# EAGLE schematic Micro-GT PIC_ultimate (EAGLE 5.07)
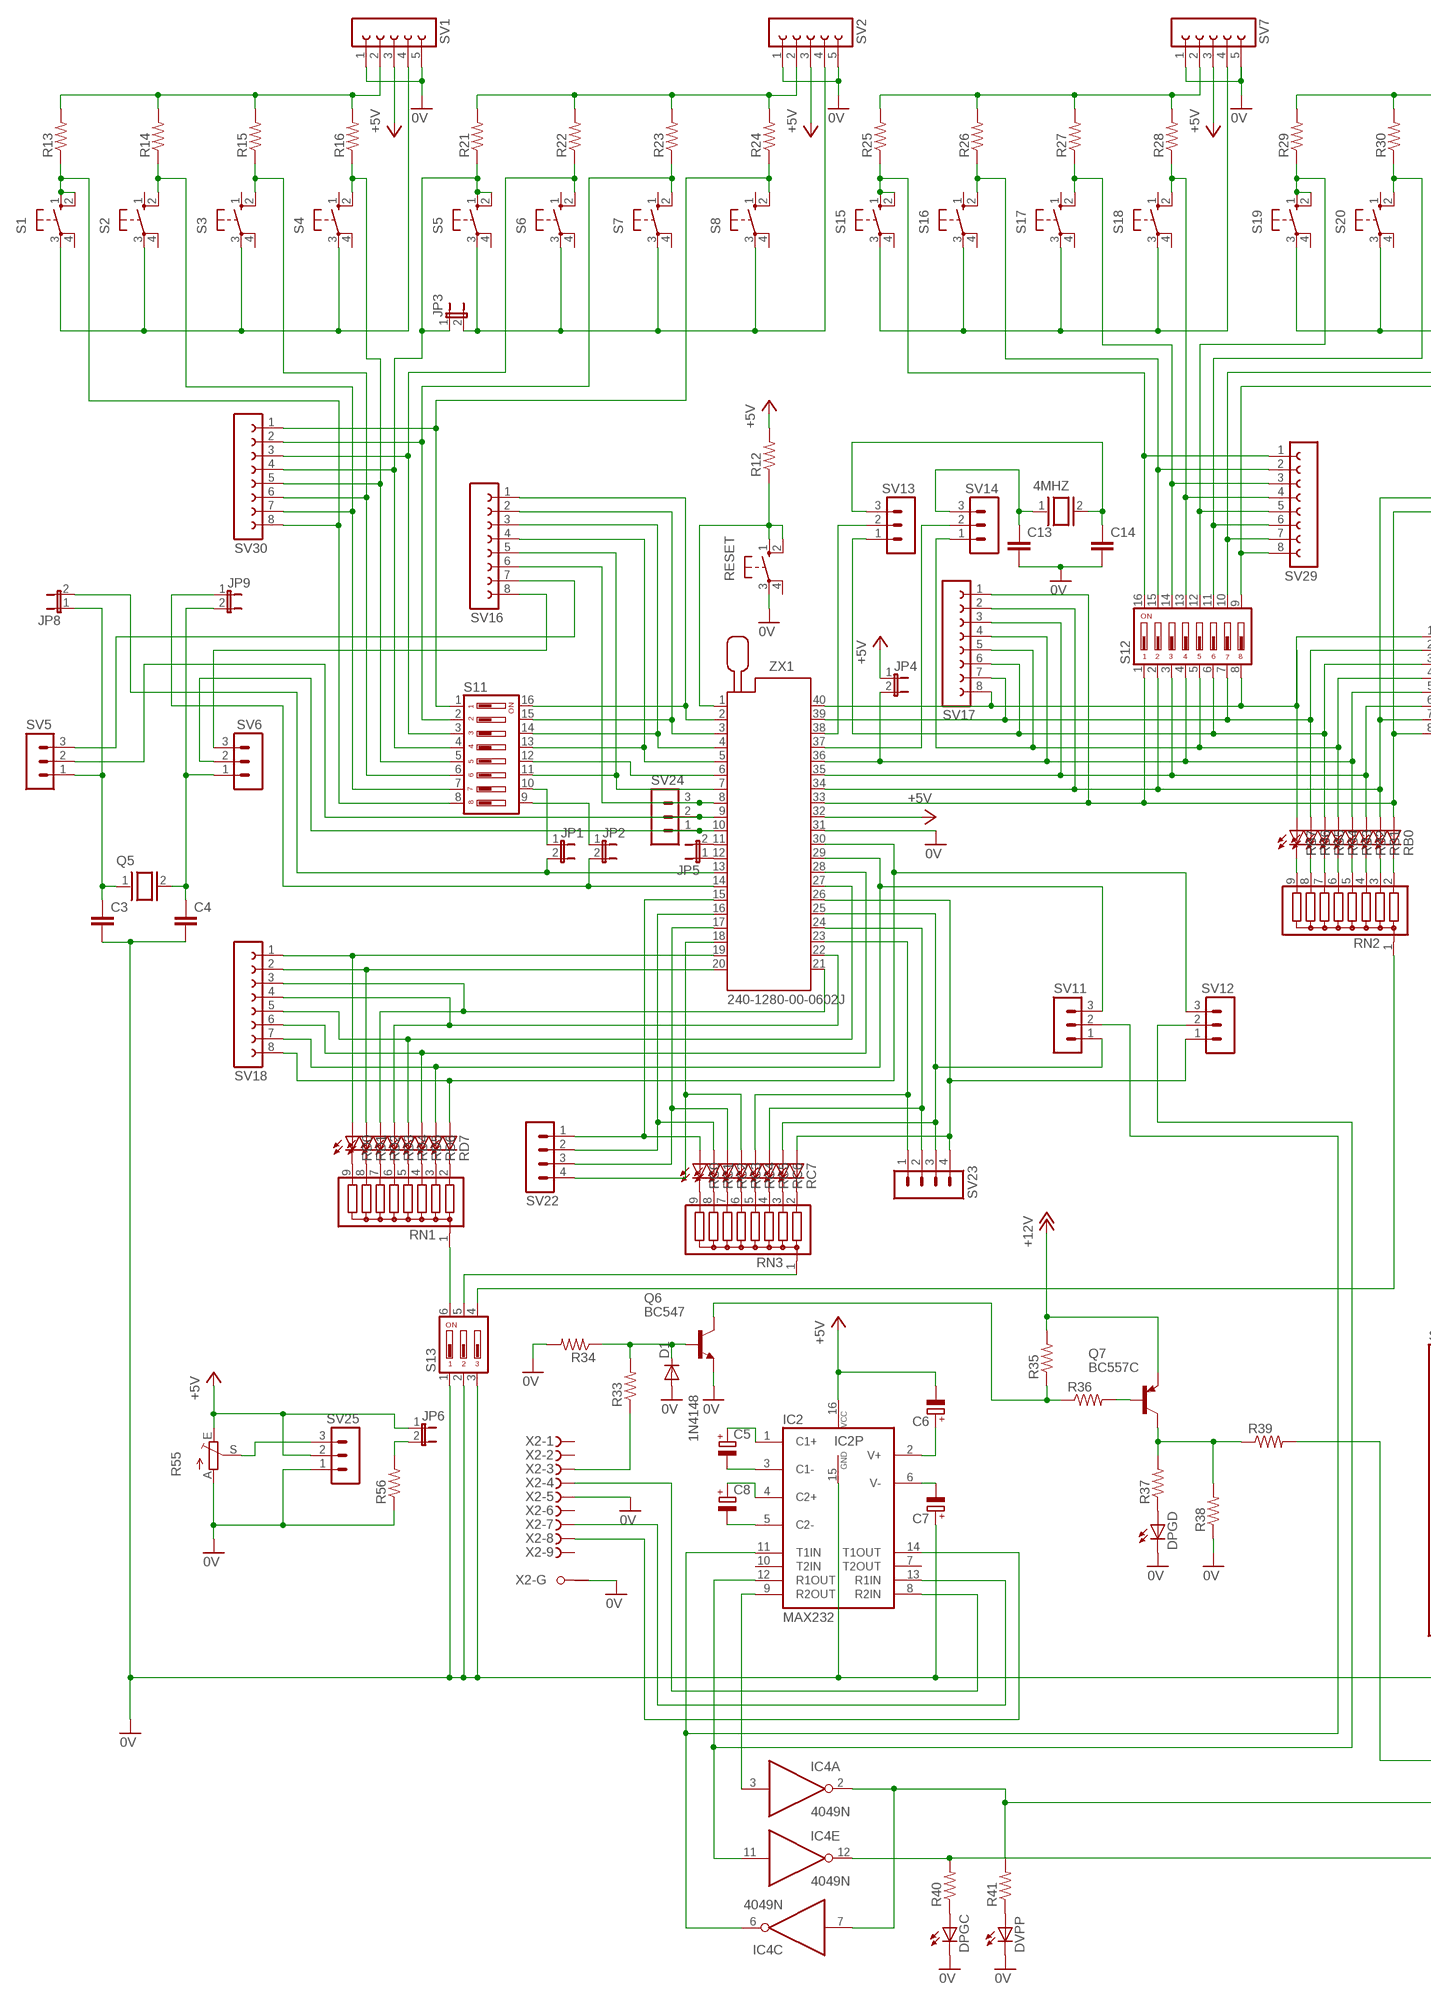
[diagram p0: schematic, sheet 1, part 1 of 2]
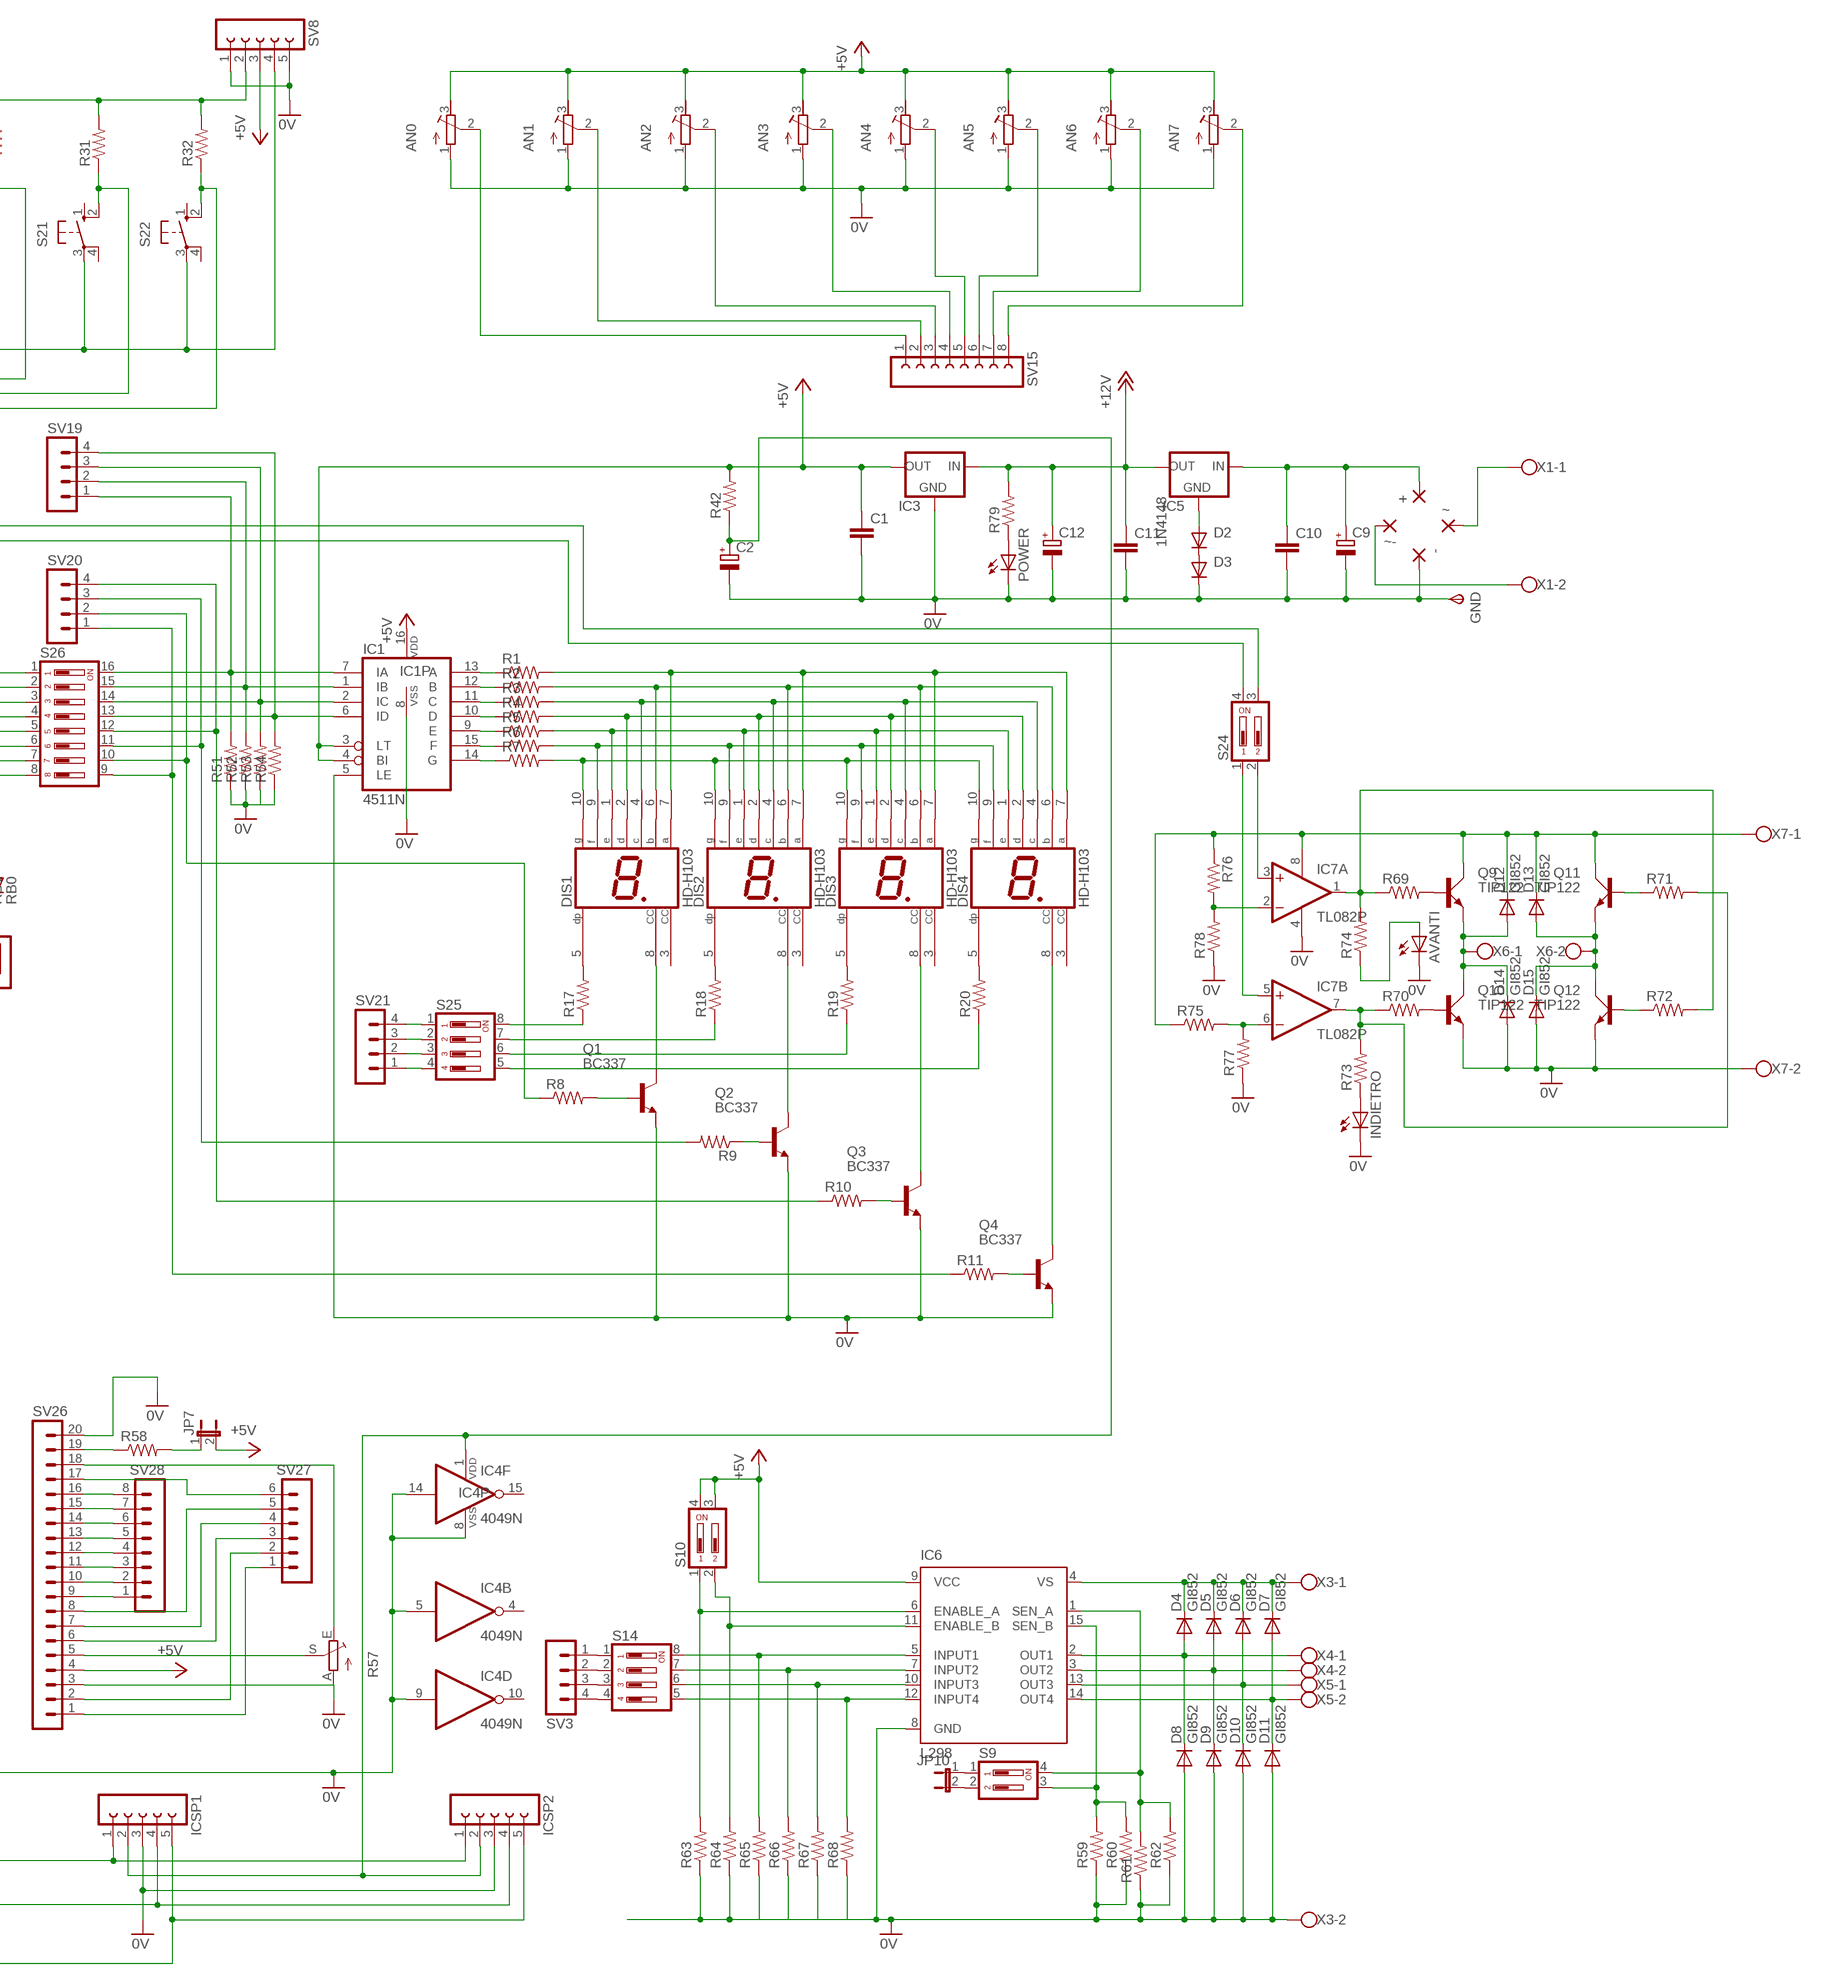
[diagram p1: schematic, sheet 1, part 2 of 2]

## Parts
4MHZ  XTAL/S  [QS]
+  1,6/0,8  [1,6/0,8]
-  1,6/0,8  [1,6/0,8]
AN0  R-TRIMM64W  [RTRIM64W]
AN1  R-TRIMM64W  [RTRIM64W]
AN2  R-TRIMM64W  [RTRIM64W]
AN3  R-TRIMM64W  [RTRIM64W]
AN4  R-TRIMM64W  [RTRIM64W]
AN5  R-TRIMM64W  [RTRIM64W]
AN6  R-TRIMM64W  [RTRIM64W]
AN7  R-TRIMM64W  [RTRIM64W]
AVANTI  LED3MM  [LED3MM]
C1  C-EU050-025X075  [C050-025X075]
C2  CPOL-EUE2.5-5  [E2,5-5]
C3  C2.5/2  [C2.5-2]
C4  C2.5/2  [C2.5-2]
C5  CPOL-EUE2.5-5  [E2,5-5]
C6  CPOL-EUE2.5-5  [E2,5-5]
C7  CPOL-EUE2.5-5  [E2,5-5]
C8  CPOL-EUE2.5-5  [E2,5-5]
C9  CPOL-EUE5-10.5  [E5-10,5]
C10  C-EU050-025X075  [C050-025X075]
C11  C-EU050-025X075  [C050-025X075]
C12  CPOL-EUE2.5-5  [E2,5-5]
C13  C2.5/2  [C2.5-2]
C14  C2.5/2  [C2.5-2]
D1  1N4148  1N4148DO35-7  [DO35-7]
D2  1N4148  1N4148DO35-7  [DO35-7]
D3  1N4148  1N4148DO35-7  [DO35-7]
D4  GI852  1N5400  [DO201-15]
D5  GI852  1N5400  [DO201-15]
D6  GI852  1N5400  [DO201-15]
D7  GI852  1N5400  [DO201-15]
D8  GI852  1N5400  [DO201-15]
D9  GI852  1N5400  [DO201-15]
D10  GI852  1N5400  [DO201-15]
D11  GI852  1N5400  [DO201-15]
D12  GI852  1N5400  [DO201-15]
D13  GI852  1N5400  [DO201-15]
D14  GI852  1N5400  [DO201-15]
D15  GI852  1N5400  [DO201-15]
DIS1  HD-H103  [HDSP-M]
DIS2  HD-H103  [HDSP-M]
DIS3  HD-H103  [HDSP-M]
DIS4  HD-H103  [HDSP-M]
DPGC  LED3MM  [LED3MM]
DPGD  LED3MM  [LED3MM]
DVPP  LED3MM  [LED3MM]
GND  TPSPAD1-13  [P1-13]
IC1  4511N  [DIL16]
IC2  MAX232  [DIL16]
IC3  78XXS  [78XXS]
IC4  4049N  [DIL16]
IC5  78XXS  [78XXS]
IC6  L298  [MULTIWATT-15]
IC7  TL082P  [DIL08]
ICSP1  FE05-1  [FE05-1]
ICSP2  FE05-1  [FE05-1]
INDIETRO  LED3MM  [LED3MM]
JP1  JP1E  [JP1]
JP2  JP1E  [JP1]
JP3  JP1E  [JP1]
JP4  JP1E  [JP1]
JP5  JP1E  [JP1]
JP6  JP1E  [JP1]
JP7  JP1E  [JP1]
JP8  JP1E  [JP1]
JP9  JP1E  [JP1]
JP10  JP1E  [JP1]
POWER  LED3MM  [LED3MM]
Q1  BC337  [TO92]
Q2  BC337  [TO92]
Q3  BC337  [TO92]
Q4  BC337  [TO92]
Q5  XTAL/S  [QS]
Q6  BC547  [TO92]
Q7  BC557C  [TO92-EBC]
Q9  TIP122  TIP41C  [TO220AV]
Q10  TIP122  TIP41C  [TO220AV]
Q11  TIP122  TIP41C  [TO220AV]
Q12  TIP122  TIP41C  [TO220AV]
R1  R-US_0207/10  [0207/10]
R2  R-US_0207/10  [0207/10]
R3  R-US_0207/10  [0207/10]
R4  R-US_0207/10  [0207/10]
R5  R-US_0207/10  [0207/10]
R6  R-US_0207/10  [0207/10]
R7  R-US_0207/10  [0207/10]
R8  R-US_0207/10  [0207/10]
R9  R-US_0207/10  [0207/10]
R10  R-US_0207/10  [0207/10]
R11  R-US_0207/10  [0207/10]
R12  R-US_0207/10  [0207/10]
R13  R-US_0207/10  [0207/10]
R14  R-US_0207/10  [0207/10]
R15  R-US_0207/10  [0207/10]
R16  R-US_0207/10  [0207/10]
R17  R-US_0207/10  [0207/10]
R18  R-US_0207/10  [0207/10]
R19  R-US_0207/10  [0207/10]
R20  R-US_0207/10  [0207/10]
R21  R-US_0207/10  [0207/10]
R22  R-US_0207/10  [0207/10]
R23  R-US_0207/10  [0207/10]
R24  R-US_0207/10  [0207/10]
R25  R-US_0207/10  [0207/10]
R26  R-US_0207/10  [0207/10]
R27  R-US_0207/10  [0207/10]
R28  R-US_0207/10  [0207/10]
R29  R-US_0207/10  [0207/10]
R30  R-US_0207/10  [0207/10]
R31  R-US_0207/10  [0207/10]
R32  R-US_0207/10  [0207/10]
R33  R-US_0207/10  [0207/10]
R34  R-US_0207/10  [0207/10]
R35  R-US_0207/10  [0207/10]
R36  R-US_0207/10  [0207/10]
R37  R-US_0207/10  [0207/10]
R38  R-US_0207/10  [0207/10]
R39  R-US_0207/10  [0207/10]
R40  R-US_0207/10  [0207/10]
R41  R-US_0207/10  [0207/10]
R42  R-US_0207/10  [0207/10]
R51  R-US_0207/10  [0207/10]
R52  R-US_0207/10  [0207/10]
R53  R-US_0207/10  [0207/10]
R54  R-US_0207/10  [0207/10]
R55  TRIM_EU-CA9V  [CA9V]
R56  R-US_0207/10  [0207/10]
R57  TRIM_EU-CA9V  [CA9V]
R58  R-US_0207/10  [0207/10]
R59  R-US_0207/10  [0207/10]
R60  R-US_0207/10  [0207/10]
R61  R-US_0207/10  [0207/10]
R62  R-US_0207/10  [0207/10]
R63  R-US_0207/10  [0207/10]
R64  R-US_0207/10  [0207/10]
R65  R-US_0207/10  [0207/10]
R66  R-US_0207/10  [0207/10]
R67  R-US_0207/10  [0207/10]
R68  R-US_0207/10  [0207/10]
R69  R-US_0207/10  [0207/10]
R70  R-US_0207/10  [0207/10]
R71  R-US_0207/10  [0207/10]
R72  R-US_0207/10  [0207/10]
R73  R-US_0207/10  [0207/10]
R74  R-US_0207/10  [0207/10]
R75  R-US_0207/10  [0207/10]
R76  R-US_0207/10  [0207/10]
R77  R-US_0207/10  [0207/10]
R78  R-US_0207/10  [0207/10]
R79  R-US_0207/10  [0207/10]
RB0  LED3MM  [LED3MM]
RB1  LED3MM  [LED3MM]
RB2  LED3MM  [LED3MM]
RB3  LED3MM  [LED3MM]
RB4  LED3MM  [LED3MM]
RB5  LED3MM  [LED3MM]
RB6  LED3MM  [LED3MM]
RB7  LED3MM  [LED3MM]
RC0  LED3MM  [LED3MM]
RC1  LED3MM  [LED3MM]
RC2  LED3MM  [LED3MM]
RC3  LED3MM  [LED3MM]
RC4  LED3MM  [LED3MM]
RC5  LED3MM  [LED3MM]
RC6  LED3MM  [LED3MM]
RC7  LED3MM  [LED3MM]
RD0  LED3MM  [LED3MM]
RD1  LED3MM  [LED3MM]
RD2  LED3MM  [LED3MM]
RD3  LED3MM  [LED3MM]
RD4  LED3MM  [LED3MM]
RD5  LED3MM  [LED3MM]
RD6  LED3MM  [LED3MM]
RD7  LED3MM  [LED3MM]
RESET  10-XX  [B3F-10XX]
RN1  G08R  [SIL9]
RN2  G08R  [SIL9]
RN3  G08R  [SIL9]
S1  10-XX  [B3F-10XX]
S2  10-XX  [B3F-10XX]
S3  10-XX  [B3F-10XX]
S4  10-XX  [B3F-10XX]
S5  10-XX  [B3F-10XX]
S6  10-XX  [B3F-10XX]
S7  10-XX  [B3F-10XX]
S8  10-XX  [B3F-10XX]
S9  DIP02YL  [DIP02YL]
S10  DIP02YL  [DIP02YL]
S11  DIP08YL  [DIP08YL]
S12  DIP08YL  [DIP08YL]
S13  DIP03YL  [DIP03YL]
S14  DIP04YL  [DIP04YL]
S15  10-XX  [B3F-10XX]
S16  10-XX  [B3F-10XX]
S17  10-XX  [B3F-10XX]
S18  10-XX  [B3F-10XX]
S19  10-XX  [B3F-10XX]
S20  10-XX  [B3F-10XX]
S21  10-XX  [B3F-10XX]
S22  10-XX  [B3F-10XX]
S24  DIP02YL  [DIP02YL]
S25  DIP04YL  [DIP04YL]
S26  DIP08YL  [DIP08YL]
SV1  FE05-1  [FE05-1]
SV2  FE05-1  [FE05-1]
SV3  MA04-1  [MA04-1]
SV5  MA03-1  [MA03-1]
SV6  MA03-1  [MA03-1]
SV7  FE05-1  [FE05-1]
SV8  FE05-1  [FE05-1]
SV11  MA03-1  [MA03-1]
SV12  MA03-1  [MA03-1]
SV13  MA03-1  [MA03-1]
SV14  MA03-1  [MA03-1]
SV15  FE08-1  [FE08]
SV16  FE08-1  [FE08]
SV17  FE08-1  [FE08]
SV18  FE08-1  [FE08]
SV19  MA04-1  [MA04-1]
SV20  MA04-1  [MA04-1]
SV21  MA04-1  [MA04-1]
SV22  MA04-1  [MA04-1]
SV23  MA04-1  [MA04-1]
SV24  MA03-1  [MA03-1]
SV25  MA03-1  [MA03-1]
SV26  MA20-1  [MA20-1]
SV27  MA06-1  [MA06-1]
SV28  MA08-1  [MA08-1]
SV29  FE08-1  [FE08]
SV30  FE08-1  [FE08]
X1  W237-102  [W237-102]
X2  F09HPS  [F09HP]
X3  W237-102  [W237-102]
X4  W237-102  [W237-102]
X5  W237-102  [W237-102]
X6  W237-102  [W237-102]
X7  W237-102  [W237-102]
ZX1  240-1280-00-0602J  [240-1280-00-0602J]
~  1,6/0,8  [1,6/0,8]
~-  1,6/0,8  [1,6/0,8]

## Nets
0V: -.1(P) AN0.1(E) AN1.1(E) AN2.1(E) AN3.1(E) AN4.1(E) AN5.1(E) AN6.1(E) AN7.1(E) AVANTI.K(C) C1.2 C2.- C3.2 C4.2 C7.+ C9.- C10.2 C11.2 C12.- C13.2 C14.2 D1.A D3.C D8.A D9.A D10.A D11.A D14.A D15.A DPGC.K(C) DPGD.K(C) DVPP.K(C) GND.TP(PP) IC1.5(LE) IC1.8(VSS) IC2.15(GND) IC3.GND IC4.5(B:I) IC4.8(P:VSS) IC4.9(D:I) IC4.14(F:I) IC6.8(GND) IC7.4(P:V-) ICSP1.3 ICSP2.3 INDIETRO.K(C) POWER.K(C) Q1.1(E) Q2.1(E) Q3.1(E) Q4.1(E) Q6.1(E) Q10.E Q12.E R34.2 R38.1 R51.1 R52.1 R53.1 R54.1 R55.A R56.1 R57.A R59.1 R60.1 R61.1 R62.1 R63.1 R64.1 R65.1 R66.1 R67.1 R68.1 R77.1 R78.1 RESET.3(P) S13.1 S13.2 S13.3 SV1.1 SV1.5 SV2.1 SV2.5 SV7.1 SV7.5 SV8.1 SV8.5 SV25.1 SV26.3 SV26.20 X2.5(-5:F) X2.G1(-G:G1) X3.2 X7.2 ZX1.31
+5V: AN0.3(A) AN1.3(A) AN2.3(A) AN3.3(A) AN4.3(A) AN5.3(A) AN6.3(A) AN7.3(A) C1.1 C6.- IC1.3(LT) IC1.4(BI) IC1.16(VDD) IC2.16(VCC) IC3.OUT IC6.9(VCC) JP4.1 JP6.1 JP7.2 R12.2 R42.2 R55.E S10.3 S10.4 SV1.3 SV2.3 SV7.3 SV8.3 SV25.2 SV26.4 ZX1.32
+12V: C11.1 C12.+ IC3.IN IC5.OUT Q7.E R35.2 R79.2
N$1: Q2.2(B) R9.1
N$2: Q3.2(B) R10.2
N$3: DIS1.5(DP) R17.2
N$4: POWER.A R79.1
N$5: IC1.13(A) R1.1
N$6: IC1.12(B) R2.1
N$7: IC1.11(C) R3.1
N$8: IC1.10(D) R4.1
N$9: IC1.9(E) R5.1
N$10: IC1.15(F) R6.1
N$11: IC1.14(G) R7.1
N$12: Q1.2(B) R8.2
N$13: DIS2.5(DP) R18.2
N$14: DIS3.5(DP) R19.2
N$15: DIS4.5(DP) R20.2
N$16: DIS1.9(F) DIS2.9(F) DIS3.9(F) DIS4.9(F) R6.2
N$17: DIS1.7(A) DIS2.7(A) DIS3.7(A) DIS4.7(A) R1.2
N$18: DIS1.6(B) DIS2.6(B) DIS3.6(B) DIS4.6(B) R2.2
N$19: DIS1.4(C) DIS2.4(C) DIS3.4(C) DIS4.4(C) R3.2
N$20: DIS1.2(D) DIS2.2(D) DIS3.2(D) DIS4.2(D) R4.2
N$21: DIS1.1(E) DIS2.1(E) DIS3.1(E) DIS4.1(E) R5.2
N$22: DIS1.10(G) DIS2.10(G) DIS3.10(G) DIS4.10(G) R7.2
N$23: IC1.7(IA) R51.2 S26.16 SV19.1
N$24: RN1.1 S13.6
N$25: D2.A IC5.GND
N$26: IC1.1(IB) R52.2 S26.15 SV19.2
N$27: DIS4.8(CC) Q4.3(C)
N$28: S1.3(P) S2.3(P) S3.3(P) S4.3(P) SV1.4
N$29: RN2.1 S13.4
N$30: RC0.K(C) RN3.9
N$31: RC1.K(C) RN3.8
N$32: RC2.K(C) RN3.7
N$33: Q4.2(B) R11.2
N$34: RB7.K(C) RN2.9
N$35: IC2.11(T1IN) IC4.6(C:O) SV11.2
N$36: IC1.2(IC) R53.2 S26.14 SV19.3
N$37: IC1.6(ID) R54.2 S26.13 SV19.4
N$38: R14.1 S2.2(S1) S11.7 SV30.7
N$39: JP1.2 JP8.2 ZX1.13
N$40: R13.1 S1.1(S) S1.2(S1) S11.8 SV30.8
N$41: JP2.2 JP9.1 ZX1.14
N$42: SV5.2 SV24.2 ZX1.9
N$43: R16.1 S4.2(S1) S11.5 SV30.5
N$44: RB6.K(C) RN2.8
N$45: C4.1 JP9.2 Q5.2 SV6.1
N$46: C3.1 JP8.1 Q5.1 SV5.1
N$47: R8.1 S26.10 SV20.2
N$48: RC3.K(C) RN3.6
N$49: RC4.K(C) RN3.5
N$50: R11.1 S26.9 SV20.1
N$51: R17.1 S25.8
N$52: R18.1 S25.7
N$53: DIS1.8(CC) Q1.3(C)
N$54: DIS2.8(CC) Q2.3(C)
N$55: DIS3.8(CC) Q3.3(C)
N$56: RC5.K(C) RN3.4
N$57: R19.1 S25.6
N$58: R20.1 S25.5
N$59: R21.2 R22.2 R23.2 R24.2 SV2.2
N$60: JP3.2 S5.3(P) S6.3(P) S7.3(P) S8.3(P) SV2.4
N$61: JP3.1 R21.1 S5.1(S) S5.2(S1) S11.4 SV30.4
N$62: R22.1 S6.2(S1) S11.3 SV30.3
N$63: R23.1 S7.2(S1) S11.2 SV30.2
N$64: R24.1 S8.2(S1) S11.1 SV30.1
N$65: RD0.K(C) RN1.9
N$66: R13.2 R14.2 R15.2 R16.2 SV1.2
N$67: R15.1 S3.2(S1) S11.6 SV30.6
N$68: SV6.2 SV24.1 ZX1.10
N$69: R25.1 S12.16 S15.1(S) S15.2(S1) SV29.1
N$70: R28.1 S12.13 S18.2(S1) SV29.4
N$71: R29.2 R30.2 R31.2 R32.2 SV8.2
N$72: S19.3(P) S20.3(P) S21.3(P) S22.3(P) SV8.4
N$73: R29.1 S12.12 S19.1(S) S19.2(S1) SV29.5
N$74: R30.1 S12.11 S20.2(S1) SV29.6
N$75: R31.1 S12.10 S21.2(S1) SV29.7
N$76: R32.1 S12.9 S22.2(S1) SV29.8
N$77: R25.2 R26.2 R27.2 R28.2 SV7.2
N$78: R26.1 S12.15 S16.2(S1) SV29.2
N$79: R27.1 S12.14 S17.2(S1) SV29.3
N$80: RD1.K(C) RN1.8
N$81: S11.16 SV16.1 ZX1.2
N$82: S11.15 SV16.2 ZX1.3
N$83: S11.14 SV16.3 ZX1.4
N$84: S11.13 SV16.4 ZX1.5
N$85: S11.12 ZX1.6
N$86: S11.11 SV16.5 ZX1.7
N$87: R12.1 RESET.1(S) RESET.2(S1) ZX1.1
N$88: RD2.K(C) RN1.7
N$89: RD3.K(C) RN1.6
N$90: JP1.1 S11.10
N$91: JP2.1 S11.9
N$92: RD4.K(C) RN1.5
N$93: RD5.K(C) RN1.4
N$94: RD6.K(C) RN1.3
N$95: RD7.K(C) RN1.2
N$96: RD0.A SV18.1 ZX1.19
N$97: S15.3(P) S16.3(P) S17.3(P) S18.3(P) SV7.4
N$98: RD1.A SV18.2 ZX1.20
N$99: RD2.A SV18.3 ZX1.21
N$100: RD3.A SV18.4 ZX1.22
N$101: RD4.A SV18.5 ZX1.27
N$102: RD5.A SV18.6 ZX1.28
N$103: RD6.A SV11.3 SV18.7 ZX1.29
N$104: RD7.A SV12.3 SV18.8 ZX1.30
N$105: RB5.K(C) RN2.7
N$106: RB4.K(C) RN2.6
N$107: RB3.K(C) RN2.5
N$108: RB2.K(C) RN2.4
N$109: RB1.K(C) RN2.3
N$110: RB0.K(C) RN2.2
N$111: RB7.A S12.8 S26.1 SV17.8 ZX1.40
N$112: RB6.A S12.7 S26.2 SV17.7 ZX1.39
N$114: RB4.A S12.5 S26.4 SV14.1 SV17.5
N$115: JP4.2 RB3.A S12.4 S26.5 SV17.4 ZX1.36
N$116: RB2.A S12.3 S26.6 SV17.3 ZX1.35
N$117: RB1.A S12.2 S24.3 S26.7 SV17.2 ZX1.34
N$118: RB0.A S12.1 S24.4 S26.8 SV17.1 ZX1.33
N$119: RC6.K(C) RN3.3
N$120: RC7.K(C) RN3.2
N$121: RC0.A SV22.1 ZX1.15
N$122: RC1.A SV22.2 ZX1.16
N$123: RC2.A SV22.3 ZX1.17
N$124: RC3.A SV22.4 ZX1.18
N$125: RC4.A SV23.1 ZX1.23
N$126: RC5.A SV23.2 ZX1.24
N$127: RC6.A SV11.1 SV23.3 ZX1.25
N$128: RC7.A SV12.1 SV23.4 ZX1.26
N$129: RN3.1 S13.5
N$130: C6.+ IC2.2(V+)
N$131: C5.+ IC2.1(C1+)
N$132: C5.- IC2.3(C1-)
N$133: C7.- IC2.6(V-)
N$134: C8.+ IC2.4(C2+)
N$135: C8.- IC2.5(C2-)
N$136: IC2.13(R1IN) X2.7(-7:F)
N$137: IC2.14(T1OUT) X2.8(-8:F)
N$138: IC2.8(R2IN) X2.4(-4:F)
N$139: R33.1 X2.3(-3:F)
N$140: D1.C Q6.2(B) R33.2 R34.1
N$141: DPGD.A R37.1
N$142: Q6.3(C) R35.1 R36.1
N$143: Q7.B R36.2
N$144: Q7.C R37.2 R38.2 R39.1
N$145: 4MHZ.2 C14.1 SV13.3
N$146: IC2.9(R2OUT) IC4.3(A:I)
N$147: +.1(P) C9.+ C10.1 IC5.IN
N$148: ICSP1.1 ICSP2.1 R39.2
N$149: 4MHZ.1 C13.1 SV14.3
N$150: IC2.12(R1OUT) IC4.11(E:I) SV12.2
N$151: RB5.A S12.6 S26.3 SV13.1 SV17.6
N$152: DPGC.A R40.1
N$153: DVPP.A R41.1
N$154: SV14.2 ZX1.37
N$155: SV13.2 ZX1.38
N$156: D2.C D3.A
N$157: IC4.2(A:O) IC4.7(C:I) ICSP1.4 ICSP2.4 R41.2
N$158: IC4.12(E:O) ICSP1.5 ICSP2.5 R40.2
N$159: JP5.1 ZX1.12
N$160: JP5.2 ZX1.11
N$161: AN0.2(S) SV15.1
N$162: C2.+ IC4.1(P:VDD) ICSP1.2 ICSP2.2 R42.1
N$163: AN1.2(S) SV15.2
N$164: AN2.2(S) SV15.3
N$165: AN3.2(S) SV15.4
N$166: AN4.2(S) SV15.5
N$167: AN5.2(S) SV15.6
N$168: AN6.2(S) SV15.7
N$169: AN7.2(S) SV15.8
N$170: SV16.6 SV24.3 ZX1.8
N$171: SV6.3 SV16.8
N$172: SV5.3 SV16.7
N$173: R55.S SV25.3
N$174: S14.1 SV3.1
N$175: JP6.2 R56.2
N$176: R57.S SV26.5
N$177: S14.2 SV3.2
N$178: R57.E SV26.18
N$179: IC6.6(ENABLE_A) R63.2 S10.1
N$180: R58.1 SV26.19
N$181: JP7.1 R58.2
N$182: IC6.11(ENABLE_B) R64.2 S10.2
N$183: SV26.1 SV27.1
N$184: SV26.2 SV27.2
N$185: SV26.6 SV27.3
N$186: SV26.7 SV27.4
N$187: SV26.8 SV27.5
N$188: SV26.17 SV27.6
N$189: SV26.9 SV28.1
N$190: SV26.10 SV28.2
N$191: SV26.11 SV28.3
N$192: SV26.12 SV28.4
N$193: SV26.13 SV28.5
N$194: SV26.14 SV28.6
N$195: SV26.15 SV28.7
N$196: SV26.16 SV28.8
N$197: D4.A D8.C IC6.2(OUT1) X4.1
N$198: D5.A D9.C IC6.3(OUT2) X4.2
N$199: D6.A D10.C IC6.13(OUT3) X5.1
N$200: D7.A D11.C IC6.14(OUT4) X5.2
N$201: D4.C D5.C D6.C D7.C IC6.4(VS) X3.1
N$202: IC6.1(SEN_A) R61.2 R62.2 S9.4
N$203: IC6.15(SEN_B) R59.2 R60.2 S9.3
N$204: S14.3 SV3.3
N$205: S14.4 SV3.4
N$206: JP10.1 S9.1
N$207: JP10.2 S9.2
N$208: IC6.12(INPUT4) R68.2 S14.5
N$209: IC6.10(INPUT3) R67.2 S14.6
N$210: IC6.7(INPUT2) R66.2 S14.7
N$211: IC6.5(INPUT1) R65.2 S14.8
N$212: IC7.3(A:+IN) S24.2
N$213: D12.C D13.C IC7.8(P:V+) Q9.C Q11.C R75.1 R76.1 X7.1
N$214: IC7.5(B:+IN) S24.1
N$215: D12.A D14.C Q9.E Q10.C X6.1
N$216: D13.A D15.C Q11.E Q12.C X6.2
N$217: Q9.B R69.2
N$218: Q10.B R70.2
N$219: Q11.B R71.1
N$220: Q12.B R72.1
N$221: INDIETRO.A R73.1
N$222: IC7.1(A:OUT) R69.1 R72.2 R74.2
N$223: AVANTI.A R74.1
N$224: IC7.7(B:OUT) R70.1 R71.2 R73.2
N$225: S25.1 SV21.4
N$226: IC7.2(A:-IN) R76.2 R78.2
N$227: IC7.6(B:-IN) R75.2 R77.2
N$228: S25.2 SV21.3
N$229: S25.3 SV21.2
N$230: S25.4 SV21.1
N$231: X1.1 ~.1(P)
N$232: X1.2 ~-.1(P)
N$233: R10.1 S26.12 SV20.4
N$234: R9.2 S26.11 SV20.3
Unconnected: DIS1.3(CC) DIS2.3(CC) DIS3.3(CC) DIS4.3(CC) IC2.7(T2OUT) IC2.10(T2IN) IC4.4(B:O) IC4.10(D:O) IC4.15(F:O) RESET.4(P1) S1.4(P1) S2.1(S) S2.4(P1) S3.1(S) S3.4(P1) S4.1(S) S4.4(P1) S5.4(P1) S6.1(S) S6.4(P1) S7.1(S) S7.4(P1) S8.1(S) S8.4(P1) S15.4(P1) S16.1(S) S16.4(P1) S17.1(S) S17.4(P1) S18.1(S) S18.4(P1) S19.4(P1) S20.1(S) S20.4(P1) S21.1(S) S21.4(P1) S22.1(S) S22.4(P1) X2.1(-1:F) X2.2(-2:F) X2.6(-6:F) X2.9(-9:F) X2.G2(-G:G2)

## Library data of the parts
4MHZ Q5 = special:XTAL/S: CRYSTAL
+ - ~ ~- = wirepad:1,6/0,8: THROUGH-HOLE PAD
AN0 AN1-AN7 = resistor:R-TRIMM: Trimm resistor
AVANTI DPGC DPGD DVPP INDIETRO POWER RB0 RB1-RB7 RC0 RC1-RC7 RD0 RD1-RD7 = led:LED: LED
C1 C10 C11 = resistor:C-EU: CAPACITOR, European symbol
C2 C5-C9 C12 = resistor:CPOL-EU: POLARIZED CAPACITOR, European symbol
C3 C4 C13 C14 = capacitor-wima:C: CAPACITOR
D1-D3 = diode:1N4148: DIODE
D4-D15 = diode:1N5400: DIODE
DIS1-DIS4 = display-hp:HD-H103: LED DISPLAY 1-character 7 segment, decimal point right
GND = testpad:TPS: TEST PIN
IC1 = 45xx:4511: BCD to 7-segment LATCH/DECODER/DRIVER
IC2 = maxim:MAX232: RS232 TRANSEIVER
IC3 IC5 = v-reg:78XXS: VOLTAGE REGULATOR
IC4 = 40xx:4049: Hex inverting BUFFER
IC6 = st-microelectronics:L298: DUAL FULL-BRIDGE DRIVER
IC7 = linear:TL082: OP AMP
ICSP1 ICSP2 SV1 SV2 SV7 SV8 = con-lsta:FE05-1: FEMALE HEADER
JP1-JP10 = jumper:JP1E: JUMPER
Q1-Q4 = transistor-npn:BC337*: NPN Transistor
Q6 = transistor-npn:BC547*: NPN Transistor
Q7 = transistor-pnp:BC557*: PNP Transistror
Q9-Q12 = transistor-power:TIP41C: NPN TRANSISTOR
R1-R42 R51-R54 R56 R58-R79 = resistor:R-US_: RESISTOR, American symbol
R55 R57 = pot:TRIM_EU-: POTENTIOMETER
RESET S1-S8 S15-S22 = switch-omron:10-XX: OMRON SWITCH
RN1-RN3 = resistor-sil:G08R: SIL RESISTOR
S9 S10 S24 = switch-dil:DIP02YL: DIL/CODE SWITCH
S11 S12 S26 = switch-dil:DIP08YL: DIL/CODE SWITCH
S13 = switch-dil:DIP03YL: DIL/CODE SWITCH
S14 S25 = switch-dil:DIP04YL: DIL/CODE SWITCH
SV3 SV19-SV23 = con-lstb:MA04-1: PIN HEADER
SV5 SV6 SV11-SV14 SV24 SV25 = con-lstb:MA03-1: PIN HEADER
SV15-SV18 SV29 SV30 = con-lsta:FE08-1: FEMALE HEADER
SV26 = con-lstb:MA20-1: PIN HEADER
SV27 = con-lstb:MA06-1: PIN HEADER
SV28 = con-lstb:MA08-1: PIN HEADER
X1 X3-X7 = con-wago-500:W237-102: WAGO SCREW CLAMP
X2 = con-subd:F09HPS: SUB-D
ZX1 = con-3m:240-?-00-0602J: Zero Insertion Force Socked Source: http://www.3M.com/ehpd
